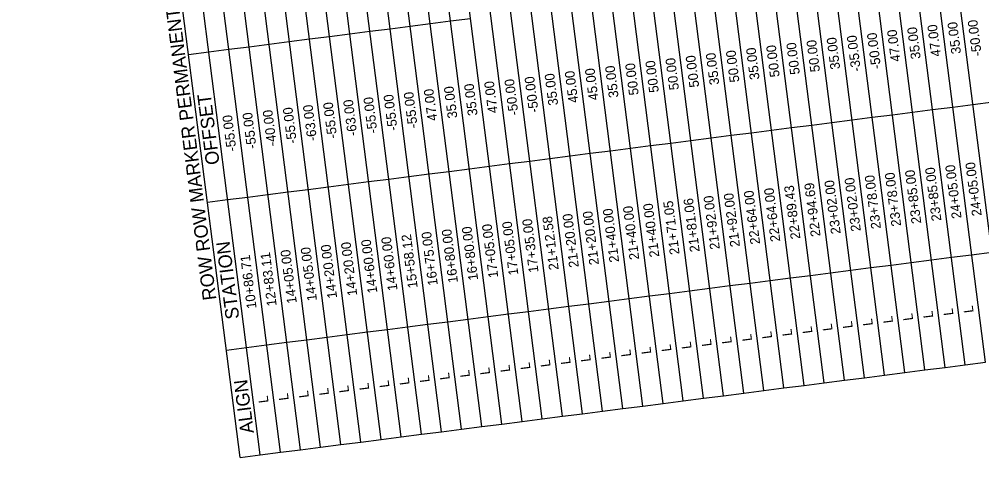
# Model space of a CAD drawing. Extents: x 2364621 to 2374814, y 792603 to 806745.
# Drawn here: x 2365933 to 2368280, y 800875 to 801956 of the extents above; entities that cross this region are included whole.
import ezdxf

# ---------------------------------------------------------------- set-up
doc = ezdxf.new("R2010")
doc.units = 0
for name, color, linetype in [('CTL Sheet Border CELL', 7, 'Continuous'), ('CTL Sheet Notes CELL', 7, 'Continuous'), ('CTL Sheet Table Cell', 7, 'Continuous'), ('CTL Sheet Text', 7, 'Continuous')]:
    doc.layers.add(name, color=color, linetype=linetype)

msp = doc.modelspace()

# ---------------------------------------------------------------- linework, layer by layer
at = {"layer": 'CTL Sheet Table Cell'}
for p, q in [((2368288.7, 801120.2), (2368054.5, 802953.9)), ((2368337.8, 801126.4), (2368103.6, 802960.2)), ((2368092.2, 801095.1), (2367858, 802928.8)), ((2368141.3, 801101.4), (2367907.1, 802935.1)), ((2368190.4, 801107.6), (2367956.2, 802941.4)), ((2368239.6, 801113.9), (2368005.4, 802947.6)), ((2367895.7, 801070), (2367661.5, 802903.7)), ((2367944.9, 801076.3), (2367710.6, 802910)), ((2367994, 801082.5), (2367759.8, 802916.3)), ((2368043.1, 801088.8), (2367808.9, 802922.5)), ((2367699.3, 801044.9), (2367465.1, 802878.6)), ((2367748.4, 801051.2), (2367514.2, 802884.9)), ((2367797.5, 801057.4), (2367563.3, 802891.2)), ((2367846.6, 801063.7), (2367612.4, 802897.4)), ((2367551.9, 801026.1), (2367317.7, 802859.8)), ((2367601, 801032.3), (2367366.8, 802866.1)), ((2367650.1, 801038.6), (2367415.9, 802872.4)), ((2367355.4, 801001), (2367121.2, 802834.7)), ((2367404.6, 801007.3), (2367170.4, 802841)), ((2367453.7, 801013.5), (2367219.5, 802847.3)), ((2367502.8, 801019.8), (2367268.6, 802853.5)), ((2367159, 800975.9), (2366924.8, 802809.6)), ((2367208.1, 800982.2), (2366973.9, 802815.9)), ((2367257.2, 800988.4), (2367023, 802822.2)), ((2367306.3, 800994.7), (2367072.1, 802828.4)), ((2366962.5, 800950.8), (2366728.3, 802784.5)), ((2367011.6, 800957.1), (2366777.4, 802790.8)), ((2367060.7, 800963.3), (2366826.5, 802797.1)), ((2367109.8, 800969.6), (2366875.6, 802803.3)), ((2366815.1, 800932), (2366580.9, 802765.7)), ((2366864.3, 800938.2), (2366630.1, 802772)), ((2366913.4, 800944.5), (2366679.2, 802778.3)), ((2366618.7, 800906.9), (2366384.5, 802740.6)), ((2366667.8, 800913.2), (2366433.6, 802746.9)), ((2366716.9, 800919.4), (2366482.7, 802753.2)), ((2366766, 800925.7), (2366531.8, 802759.4)), ((2366471.3, 800888.1), (2366237.1, 802721.8)), ((2366520.4, 800894.3), (2366286.2, 802728.1)), ((2366569.6, 800900.6), (2366335.3, 802734.3)), ((2366837, 801933.1), (2366886.1, 801939.4)), ((2366886.1, 801939.4), (2366935.3, 801945.7)), ((2366935.3, 801945.7), (2366984.4, 801952)), ((2366984.4, 801952), (2367033.5, 801958.2)), ((2366689.7, 801914.3), (2366738.8, 801920.6)), ((2366738.8, 801920.6), (2366787.9, 801926.9)), ((2366787.9, 801926.9), (2366837, 801933.1)), ((2366493.2, 801889.2), (2366542.3, 801895.5)), ((2366542.3, 801895.5), (2366591.4, 801901.8)), ((2366591.4, 801901.8), (2366640.6, 801908.1)), ((2366640.6, 801908.1), (2366689.7, 801914.3)), ((2366345.8, 801870.4), (2366395, 801876.7)), ((2366395, 801876.7), (2366444.1, 801883)), ((2366444.1, 801883), (2366493.2, 801889.2)), ((2368258.3, 801748.6), (2368307.5, 801754.9)), ((2368061.9, 801723.5), (2368111, 801729.8)), ((2368111, 801729.8), (2368160.1, 801736.1)), ((2368160.1, 801736.1), (2368209.2, 801742.3)), ((2368209.2, 801742.3), (2368258.3, 801748.6)), ((2367865.4, 801698.4), (2367914.5, 801704.7)), ((2367914.5, 801704.7), (2367963.6, 801711)), ((2367963.6, 801711), (2368012.7, 801717.2)), ((2368012.7, 801717.2), (2368061.9, 801723.5)), ((2367718, 801679.6), (2367767.2, 801685.9)), ((2367767.2, 801685.9), (2367816.3, 801692.1)), ((2367816.3, 801692.1), (2367865.4, 801698.4)), ((2367521.6, 801654.5), (2367570.7, 801660.8)), ((2367570.7, 801660.8), (2367619.8, 801667.1)), ((2367619.8, 801667.1), (2367668.9, 801673.3)), ((2367668.9, 801673.3), (2367718, 801679.6)), ((2367325.1, 801629.4), (2367374.2, 801635.7)), ((2367374.2, 801635.7), (2367423.3, 801642)), ((2367423.3, 801642), (2367472.4, 801648.2)), ((2367472.4, 801648.2), (2367521.6, 801654.5)), ((2367177.7, 801610.6), (2367226.9, 801616.9)), ((2367226.9, 801616.9), (2367276, 801623.1)), ((2367276, 801623.1), (2367325.1, 801629.4)), ((2366981.3, 801585.5), (2367030.4, 801591.8)), ((2367030.4, 801591.8), (2367079.5, 801598)), ((2367079.5, 801598), (2367128.6, 801604.3)), ((2367128.6, 801604.3), (2367177.7, 801610.6)), ((2366784.8, 801560.4), (2366833.9, 801566.7)), ((2366833.9, 801566.7), (2366883, 801573)), ((2366883, 801573), (2366932.2, 801579.2)), ((2366932.2, 801579.2), (2366981.3, 801585.5)), ((2366588.3, 801535.3), (2366637.4, 801541.6)), ((2366637.4, 801541.6), (2366686.6, 801547.9)), ((2366686.6, 801547.9), (2366735.7, 801554.1)), ((2366735.7, 801554.1), (2366784.8, 801560.4)), ((2366441, 801516.5), (2366490.1, 801522.8)), ((2366490.1, 801522.8), (2366539.2, 801529)), ((2366539.2, 801529), (2366588.3, 801535.3)), ((2366391.9, 801510.2), (2366441, 801516.5)), ((2368206.1, 801375.9), (2368255.2, 801382.1)), ((2368255.2, 801382.1), (2368304.3, 801388.4)), ((2368009.6, 801350.8), (2368058.7, 801357)), ((2368058.7, 801357), (2368107.9, 801363.3)), ((2368107.9, 801363.3), (2368157, 801369.6)), ((2368157, 801369.6), (2368206.1, 801375.9)), ((2367813.2, 801325.7), (2367862.3, 801331.9)), ((2367862.3, 801331.9), (2367911.4, 801338.2)), ((2367911.4, 801338.2), (2367960.5, 801344.5)), ((2367960.5, 801344.5), (2368009.6, 801350.8)), ((2367616.7, 801300.6), (2367665.8, 801306.9)), ((2367665.8, 801306.9), (2367714.9, 801313.1)), ((2367714.9, 801313.1), (2367764, 801319.4)), ((2367764, 801319.4), (2367813.2, 801325.7)), ((2367469.3, 801281.8), (2367518.5, 801288)), ((2367518.5, 801288), (2367567.6, 801294.3)), ((2367567.6, 801294.3), (2367616.7, 801300.6)), ((2367272.9, 801256.7), (2367322, 801262.9)), ((2367322, 801262.9), (2367371.1, 801269.2)), ((2367371.1, 801269.2), (2367420.2, 801275.5)), ((2367420.2, 801275.5), (2367469.3, 801281.8)), ((2367076.4, 801231.6), (2367125.5, 801237.8)), ((2367125.5, 801237.8), (2367174.6, 801244.1)), ((2367174.6, 801244.1), (2367223.7, 801250.4)), ((2367223.7, 801250.4), (2367272.9, 801256.7)), ((2366879.9, 801206.5), (2366929, 801212.8)), ((2366929, 801212.8), (2366978.2, 801219)), ((2366978.2, 801219), (2367027.3, 801225.3)), ((2367027.3, 801225.3), (2367076.4, 801231.6)), ((2366732.6, 801187.7), (2366781.7, 801193.9)), ((2366781.7, 801193.9), (2366830.8, 801200.2)), ((2366830.8, 801200.2), (2366879.9, 801206.5)), ((2366536.1, 801162.6), (2366585.2, 801168.8)), ((2366585.2, 801168.8), (2366634.3, 801175.1)), ((2366634.3, 801175.1), (2366683.4, 801181.4)), ((2366683.4, 801181.4), (2366732.6, 801187.7)), ((2366437.9, 801150), (2366487, 801156.3)), ((2366487, 801156.3), (2366536.1, 801162.6)), ((2368239.6, 801113.9), (2368288.7, 801120.2)), ((2368043.1, 801088.8), (2368092.2, 801095.1)), ((2368092.2, 801095.1), (2368141.3, 801101.4)), ((2368141.3, 801101.4), (2368190.4, 801107.6)), ((2368190.4, 801107.6), (2368239.6, 801113.9)), ((2367895.7, 801070), (2367944.9, 801076.3)), ((2367944.9, 801076.3), (2367994, 801082.5)), ((2367994, 801082.5), (2368043.1, 801088.8)), ((2367699.3, 801044.9), (2367748.4, 801051.2)), ((2367748.4, 801051.2), (2367797.5, 801057.4)), ((2367797.5, 801057.4), (2367846.6, 801063.7)), ((2367846.6, 801063.7), (2367895.7, 801070)), ((2367502.8, 801019.8), (2367551.9, 801026.1)), ((2367551.9, 801026.1), (2367601, 801032.3)), ((2367601, 801032.3), (2367650.1, 801038.6)), ((2367650.1, 801038.6), (2367699.3, 801044.9)), ((2367306.3, 800994.7), (2367355.4, 801001)), ((2367355.4, 801001), (2367404.6, 801007.3)), ((2367404.6, 801007.3), (2367453.7, 801013.5)), ((2367453.7, 801013.5), (2367502.8, 801019.8)), ((2367159, 800975.9), (2367208.1, 800982.2)), ((2367208.1, 800982.2), (2367257.2, 800988.4)), ((2367257.2, 800988.4), (2367306.3, 800994.7)), ((2366962.5, 800950.8), (2367011.6, 800957.1)), ((2367011.6, 800957.1), (2367060.7, 800963.3)), ((2367060.7, 800963.3), (2367109.8, 800969.6)), ((2367109.8, 800969.6), (2367159, 800975.9)), ((2366766, 800925.7), (2366815.1, 800932)), ((2366815.1, 800932), (2366864.3, 800938.2)), ((2366864.3, 800938.2), (2366913.4, 800944.5)), ((2366913.4, 800944.5), (2366962.5, 800950.8)), ((2366569.6, 800900.6), (2366618.7, 800906.9)), ((2366618.7, 800906.9), (2366667.8, 800913.2)), ((2366667.8, 800913.2), (2366716.9, 800919.4)), ((2366716.9, 800919.4), (2366766, 800925.7)), ((2366471.3, 800888.1), (2366520.4, 800894.3)), ((2366520.4, 800894.3), (2366569.6, 800900.6))]:
    msp.add_line(p, q, dxfattribs=at)

# ---------------------------------------------------------------- texts
at = {"layer": 'CTL Sheet Border CELL'}
msp.add_text('SURVEY CONTROL SHEET U-4762', height=156.286, rotation=97.2784, dxfattribs=at).set_placement((2366164.2, 797911.8))
at = {"layer": 'CTL Sheet Notes CELL'}
for s, height, p in [('ROW ROW MARKER PERMANENT EASEMENT', 33.011, (2366413.8, 801273.3)), ('OFFSET', 33.01, (2366421.5, 801603.5)), ('STATION', 33.01, (2366469.6, 801227.1)), ('ALIGN', 33.01, (2366505.2, 800948.5))]:
    msp.add_text(s, height=height, rotation=97.2784, dxfattribs=at).set_placement(p)
at = {"layer": 'CTL Sheet Text'}
for s, height, p in [('47.00', 23.58, (2368180.3, 801866.6)), ('35.00', 23.58, (2368229.4, 801872.9)), ('-50.00', 23.58, (2368280, 801867.6)), ('-35.00', 23.58, (2367985.3, 801829.9)), ('-50.00', 23.58, (2368034.4, 801836.2)), ('47.00', 23.58, (2368082, 801854.1)), ('35.00', 23.58, (2368131.1, 801860.4)), ('50.00', 23.58, (2367787.3, 801816.5)), ('50.00', 23.58, (2367836.4, 801822.7)), ('50.00', 23.58, (2367885.6, 801829)), ('35.00', 23.58, (2367934.7, 801835.3)), ('35.00', 23.58, (2367640, 801797.6)), ('50.00', 23.58, (2367689.1, 801803.9)), ('35.00', 23.58, (2367738.2, 801810.2)), ('50.00', 23.58, (2367443.5, 801772.5)), ('50.00', 23.58, (2367492.6, 801778.8)), ('50.00', 23.58, (2367541.7, 801785.1)), ('50.00', 23.58, (2367590.9, 801791.4)), ('35.00', 23.58, (2367247, 801747.4)), ('45.00', 23.58, (2367296.1, 801753.7)), ('45.00', 23.58, (2367345.3, 801760)), ('35.00', 23.58, (2367394.4, 801766.3)), ('35.00', 23.58, (2367050.6, 801722.4)), ('47.00', 23.58, (2367099.7, 801728.6)), ('-50.00', 23.58, (2367150.3, 801723.3)), ('-50.00', 23.58, (2367199.4, 801729.6)), ('-55.00', 23.58, (2366904.7, 801691.9)), ('47.00', 23.58, (2366952.3, 801709.8)), ('35.00', 23.58, (2367001.4, 801716.1)), ('-55.00', 23.58, (2366708.2, 801666.8)), ('-63.00', 23.58, (2366757.3, 801673.1)), ('-55.00', 23.58, (2366806.4, 801679.4)), ('-55.00', 23.58, (2366855.6, 801685.7)), ('-55.00', 23.58, (2366511.7, 801641.7)), ('-40.00', 23.58, (2366560.9, 801648)), ('-55.00', 23.58, (2366610, 801654.3)), ('-63.00', 23.58, (2366659.1, 801660.6)), ('-55.00', 23.58, (2366462.6, 801635.5)), ('23+85.00', 23.58, (2368132.5, 801459.1)), ('23+85.00', 23.58, (2368181.6, 801465.4)), ('24+05.00', 23.58, (2368230.7, 801471.6)), ('24+05.00', 23.58, (2368279.8, 801477.9)), ('23+02.00', 23.58, (2367985.1, 801440.3)), ('23+78.00', 23.58, (2368034.2, 801446.5)), ('23+78.00', 23.58, (2368083.4, 801452.8)), ('22+64.00', 23.58, (2367788.7, 801415.2)), ('22+89.43', 23.58, (2367837.8, 801421.4)), ('22+94.69', 23.58, (2367886.9, 801427.7)), ('23+02.00', 23.58, (2367936, 801434)), ('21+81.06', 23.58, (2367592.2, 801390.1)), ('21+92.00', 23.58, (2367641.3, 801396.4)), ('21+92.00', 23.58, (2367690.4, 801402.6)), ('22+64.00', 23.58, (2367739.5, 801408.9)), ('21+40.00', 23.58, (2367395.7, 801365)), ('21+40.00', 23.58, (2367444.8, 801371.3)), ('21+40.00', 23.58, (2367493.9, 801377.5)), ('21+71.05', 23.58, (2367543.1, 801383.8)), ('21+12.58', 23.58, (2367248.4, 801346.2)), ('21+20.00', 23.58, (2367297.5, 801352.4)), ('21+20.00', 23.58, (2367346.6, 801358.7)), ('16+80.00', 23.58, (2367051.9, 801321.1)), ('17+05.00', 23.58, (2367101, 801327.3)), ('17+05.00', 23.58, (2367150.1, 801333.6)), ('17+35.00', 23.58, (2367199.2, 801339.9)), ('14+60.00', 23.58, (2366855.4, 801296)), ('15+58.12', 23.58, (2366904.5, 801302.3)), ('16+75.00', 23.58, (2366953.6, 801308.5)), ('16+80.00', 23.58, (2367002.8, 801314.8)), ('14+05.00', 23.58, (2366658.9, 801270.9)), ('14+20.00', 23.58, (2366708.1, 801277.2)), ('14+20.00', 23.58, (2366757.2, 801283.4)), ('14+60.00', 23.58, (2366806.3, 801289.7)), ('10+86.71', 23.58, (2366511.6, 801252.1)), ('12+83.11', 23.58, (2366560.7, 801258.3)), ('14+05.00', 23.58, (2366609.8, 801264.6)), ('L', 23.6, (2368112.7, 801223)), ('L', 23.6, (2368161.8, 801229.2)), ('L', 23.6, (2368211, 801235.5)), ('L', 23.6, (2368260.1, 801241.8)), ('L', 23.6, (2367916.2, 801197.9)), ('L', 23.6, (2367965.4, 801204.1)), ('L', 23.6, (2368014.5, 801210.4)), ('L', 23.6, (2368063.6, 801216.7)), ('L', 23.6, (2367719.8, 801172.8)), ('L', 23.6, (2367768.9, 801179)), ('L', 23.6, (2367818, 801185.3)), ('L', 23.6, (2367867.1, 801191.6)), ('L', 23.6, (2367572.4, 801153.9)), ('L', 23.6, (2367621.5, 801160.2)), ('L', 23.6, (2367670.7, 801166.5)), ('L', 23.6, (2367376, 801128.9)), ('L', 23.6, (2367425.1, 801135.1)), ('L', 23.6, (2367474.2, 801141.4)), ('L', 23.6, (2367523.3, 801147.7)), ('L', 23.6, (2367179.5, 801103.8)), ('L', 23.6, (2367228.6, 801110)), ('L', 23.6, (2367277.7, 801116.3)), ('L', 23.6, (2367326.8, 801122.6)), ('L', 23.6, (2366983, 801078.7)), ('L', 23.6, (2367032.1, 801084.9)), ('L', 23.6, (2367081.2, 801091.2)), ('L', 23.6, (2367130.4, 801097.5)), ('L', 23.6, (2366835.7, 801059.8)), ('L', 23.6, (2366884.8, 801066.1)), ('L', 23.6, (2366933.9, 801072.4)), ('L', 23.6, (2366639.2, 801034.8)), ('L', 23.6, (2366688.3, 801041)), ('L', 23.6, (2366737.4, 801047.3)), ('L', 23.6, (2366786.5, 801053.6)), ('L', 23.6, (2366540.9, 801022.2)), ('L', 23.6, (2366590.1, 801028.5))]:
    msp.add_text(s, height=height, rotation=97.2784, dxfattribs=at).set_placement(p)

doc.saveas('drawing.dxf')
